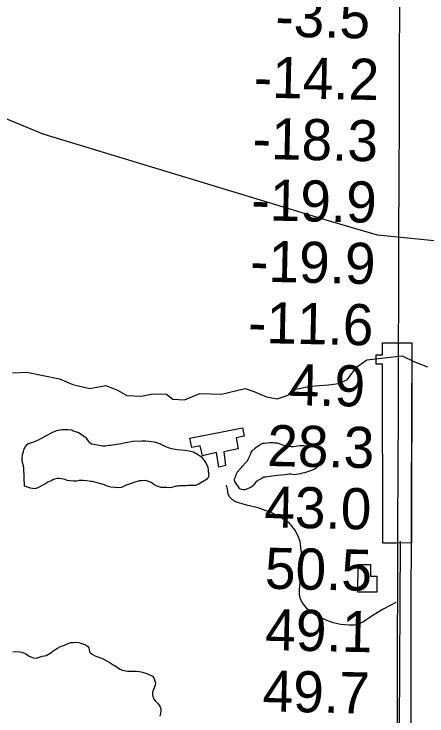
# Model space of a CAD drawing. Extents: x 3146026 to 3183936, y 897894 to 923344.
# Drawn here: x 3160093 to 3160766, y 910893 to 912037 of the extents above; entities that cross this region are included whole.
import ezdxf

# ---------------------------------------------------------------- set-up
doc = ezdxf.new("R2010")
doc.units = 0
for name, color, linetype in [('V-BLDG-OTLN', 7, 'Continuous'), ('V-CHAN-DOCK', 7, 'Continuous'), ('V-GRID-MAJR', 7, 'Continuous'), ('V-RIVR-EDGE', 7, 'Continuous'), ('V-RIVR-RANG', 7, 'Continuous'), ('V-ROAD-CNTR', 7, 'Continuous'), ('V-SITE-STRC', 7, 'Continuous'), ('V-SITE-VEGE', 7, 'Continuous'), ('V-TOPO-BNDY', 7, 'Continuous'), ('V-TOPO-SHOR', 7, 'Continuous')]:
    doc.layers.add(name, color=color, linetype=linetype)

msp = doc.modelspace()

# ---------------------------------------------------------------- linework, layer by layer
at = {"layer": 'V-BLDG-OTLN'}
msp.add_lwpolyline([(3160653.847000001, 911094.7049999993), (3160654.001000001, 911139.5099999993), (3160674.080000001, 911139.4399999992), (3160674.014000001, 911120.7769999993), (3160684.629000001, 911120.7399999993), (3160684.539000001, 911094.5969999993)], close=True, dxfattribs=at)
at = {"layer": 'V-CHAN-DOCK'}
msp.add_lwpolyline([(3160716.291000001, 911174.2719999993), (3160694.164000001, 911174.5569999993), (3160693.7690000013, 911466.0689999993), (3160683.320000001, 911466.2149999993), (3160683.646000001, 911481.3759999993), (3160693.888000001, 911481.6379999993), (3160693.779000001, 911500.8959999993), (3160741.510000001, 911500.9569999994), (3160740.869000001, 911174.8169999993), (3160716.291000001, 911174.2719999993)], dxfattribs=at)
msp.add_lwpolyline([(3160427.261000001, 911298.0469999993), (3160423.441000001, 911322.1989999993), (3160400.119000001, 911316.5389999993), (3160396.3400000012, 911332.9059999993), (3160383.040000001, 911330.1679999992), (3160379.471000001, 911345.5139999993), (3160465.827000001, 911362.5879999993), (3160468.563000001, 911349.0809999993), (3160455.470000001, 911345.9359999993), (3160458.642000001, 911328.3349999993), (3160434.906000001, 911323.2889999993), (3160437.898000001, 911300.9759999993)], close=True, dxfattribs=at)
at = {"layer": 'V-GRID-MAJR'}
msp.add_spline([(3160706.023, 907303.2220000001), (3160713.04, 909400.895), (3160733.322, 915463.759), (3160753.6040000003, 921526.669), (3160753.614, 921529.706)], degree=3, dxfattribs=at)
at = {"layer": 'V-RIVR-EDGE'}
msp.add_lwpolyline([(3160090.500730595, 911452.2093146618), (3160114.2982461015, 911452.9436602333), (3160167.416153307, 911442.5008450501), (3160189.2052088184, 911432.9286871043), (3160216.5544055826, 911426.5155404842), (3160242.7422637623, 911431.606520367), (3160261.7590939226, 911423.6275973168), (3160276.808037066, 911414.8652957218), (3160300.6016299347, 911414.013271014), (3160319.25128731, 911417.9331057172), (3160341.8551024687, 911417.0840229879), (3160352.146896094, 911409.1266744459), (3160370.7838048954, 911407.890805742), (3160395.7956145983, 911418.5370235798), (3160431.4860039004, 911417.2589865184), (3160469.9780383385, 911426.2854916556), (3160484.244583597, 911421.8876696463), (3160504.449230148, 911413.1126194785), (3160522.287069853, 911409.4991566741), (3160540.149426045, 911415.8005081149), (3160546.9120935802, 911424.1122808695), (3160576.2756342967, 911430.3851931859), (3160606.0249803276, 911432.2946065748), (3160621.894567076, 911434.6349356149), (3160636.5851633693, 911441.340724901), (3160651.3091020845, 911461.5306615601), (3160668.3920023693, 911473.3862702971), (3160725.9145962, 911479.9861483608), (3160745.719708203, 911470.0223011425), (3160767.1160937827, 911462.0374941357)], dxfattribs=at)
at = {"layer": 'V-ROAD-CNTR'}
for points in [[(3160715.496000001, 911077.7909999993), (3160695.002000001, 911067.1049999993), (3160675.296000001, 911055.0279999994), (3160662.818000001, 911046.3599999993), (3160655.351000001, 911042.9299999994), (3160647.370000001, 911040.9929999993), (3160639.180000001, 911040.6199999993), (3160625.681000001, 911042.0119999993), (3160613.610000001, 911044.8429999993), (3160602.047000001, 911049.1349999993), (3160598.672000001, 911050.7139999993), (3160588.989000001, 911054.7649999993), (3160579.968000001, 911060.2269999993), (3160571.813000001, 911066.9759999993), (3160567.006000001, 911072.0479999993), (3160562.744000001, 911077.9219999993), (3160559.861000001, 911084.5919999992), (3160558.497000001, 911091.7379999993), (3160558.665000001, 911098.6339999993), (3160561.827000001, 911132.9049999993), (3160562.322000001, 911140.6479999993), (3160561.6610000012, 911158.7999999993), (3160559.660000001, 911177.3029999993), (3160555.976000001, 911187.0989999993), (3160550.856000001, 911196.2229999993), (3160544.423000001, 911204.4639999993), (3160542.082000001, 911206.9109999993), (3160528.795000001, 911215.6849999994), (3160514.704000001, 911223.0879999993), (3160499.948000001, 911229.0499999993), (3160491.138000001, 911231.8229999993), (3160471.872000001, 911236.3939999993), (3160454.206000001, 911242.0649999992), (3160449.062000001, 911245.1109999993), (3160444.898000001, 911249.3849999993), (3160442.049000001, 911254.4949999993), (3160441.382000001, 911262.6559999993), (3160439.7150000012, 911269.2319999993)], [(3160722.593518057, 911177.624616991), (3160721.038521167, 910872.1702279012)]]:
    msp.add_lwpolyline(points, dxfattribs=at)
at = {"layer": 'V-SITE-STRC'}
for p, q in [((3160741.510000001, 911500.9569999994), (3160740.601000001, 911241.4099999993)), ((3160740.601000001, 911241.4099999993), (3160740.181000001, 911022.8229999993)), ((3160740.181000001, 911022.8229999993), (3160739.978000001, 910838.4489999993))]:
    msp.add_line(p, q, dxfattribs=at)
at = {"layer": 'V-SITE-VEGE'}
for points in [[(3160398.812000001, 911315.2999999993), (3160406.003000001, 911305.2689999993), (3160408.978000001, 911298.1559999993), (3160409.849000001, 911293.1239999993), (3160409.859000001, 911291.0249999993), (3160410.717000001, 911287.2539999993), (3160410.312000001, 911284.7329999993), (3160410.326000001, 911282.2159999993), (3160408.657000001, 911280.5289999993), (3160406.992000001, 911278.4209999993), (3160397.790000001, 911272.9159999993), (3160393.192000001, 911269.9549999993), (3160389.004000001, 911268.6709999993), (3160381.453000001, 911268.2099999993), (3160377.259000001, 911268.1849999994), (3160373.904000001, 911267.7469999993), (3160371.383000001, 911268.1529999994), (3160369.288000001, 911267.7229999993), (3160366.771000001, 911267.7079999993), (3160362.995000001, 911267.6879999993), (3160360.480000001, 911267.2539999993), (3160357.963000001, 911267.2389999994), (3160350.002000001, 911265.0969999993), (3160345.810000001, 911264.6549999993), (3160341.611000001, 911265.0519999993), (3160338.675000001, 911265.0339999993), (3160332.799000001, 911265.4209999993), (3160326.493000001, 911267.4849999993), (3160323.128000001, 911269.1439999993), (3160321.025000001, 911269.9709999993), (3160316.810000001, 911273.3029999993), (3160309.663000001, 911276.2009999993), (3160306.724000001, 911276.6049999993), (3160300.850000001, 911276.1519999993), (3160297.495000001, 911276.1339999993), (3160295.398000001, 911275.7019999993), (3160291.630000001, 911274.4239999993), (3160288.699000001, 911273.1479999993), (3160284.091000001, 911271.8639999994), (3160276.137000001, 911268.8819999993), (3160268.187000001, 911265.0599999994), (3160261.895000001, 911264.6079999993), (3160257.277000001, 911265.0009999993), (3160250.979000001, 911265.8059999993), (3160246.779000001, 911266.6209999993), (3160239.627000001, 911269.9359999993), (3160236.266000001, 911270.7579999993), (3160223.239000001, 911274.4599999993), (3160220.300000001, 911274.8659999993), (3160217.781000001, 911274.8499999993), (3160211.901000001, 911276.0759999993), (3160205.186000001, 911276.4569999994), (3160199.312000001, 911276.4269999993), (3160195.542000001, 911275.5659999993), (3160190.086000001, 911275.5359999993), (3160184.630000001, 911275.9249999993), (3160179.5900000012, 911276.7359999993), (3160176.647000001, 911277.9789999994), (3160170.345000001, 911279.2019999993), (3160166.147000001, 911280.0169999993), (3160163.208000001, 911279.9999999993), (3160159.020000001, 911278.7179999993), (3160156.509000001, 911277.4459999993), (3160154.418000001, 911276.1749999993), (3160150.650000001, 911274.8969999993), (3160148.141000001, 911273.6229999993), (3160143.121000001, 911270.6569999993), (3160137.684000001, 911267.6919999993), (3160134.3400000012, 911265.5739999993), (3160129.316000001, 911263.4479999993), (3160126.801000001, 911263.0139999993), (3160120.079000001, 911264.2369999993), (3160116.719000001, 911265.0559999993), (3160110.413000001, 911267.5379999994), (3160109.493000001, 911281.7979999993), (3160109.4110000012, 911296.4829999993), (3160108.549000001, 911300.6749999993), (3160106.843000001, 911305.7009999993), (3160106.403000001, 911309.4729999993), (3160106.386000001, 911312.4119999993), (3160107.189000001, 911318.7099999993), (3160108.420000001, 911323.7519999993), (3160109.657000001, 911327.9539999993), (3160111.730000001, 911332.1609999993), (3160115.901000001, 911336.3799999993), (3160118.834000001, 911337.2359999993), (3160125.533000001, 911339.7899999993), (3160130.557000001, 911341.9149999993), (3160133.070000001, 911342.7689999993), (3160145.198000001, 911349.5499999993), (3160155.241000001, 911354.6419999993), (3160162.354000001, 911358.0369999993), (3160171.156000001, 911359.7619999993), (3160180.807000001, 911359.8169999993), (3160187.524000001, 911359.0159999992), (3160189.627000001, 911357.7689999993), (3160198.0360000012, 911354.8789999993), (3160204.350000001, 911351.1379999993), (3160207.725000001, 911348.2189999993), (3160209.409000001, 911346.9719999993), (3160214.4820000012, 911340.2849999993)], [(3160214.4820000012, 911340.2849999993), (3160217.433000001, 911337.7869999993), (3160219.5360000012, 911336.5369999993), (3160229.197000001, 911334.9129999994), (3160237.1780000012, 911333.2789999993), (3160242.214000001, 911332.8879999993), (3160248.4990000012, 911334.1819999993), (3160250.598000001, 911334.1919999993), (3160260.658000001, 911335.9269999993), (3160268.205000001, 911336.8099999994), (3160272.813000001, 911338.0939999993), (3160287.065000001, 911340.6909999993), (3160301.7490000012, 911341.1899999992), (3160308.039000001, 911341.2249999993), (3160312.239000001, 911340.8299999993), (3160321.476000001, 911339.6239999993), (3160326.940000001, 911337.9749999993), (3160331.564000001, 911336.3219999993), (3160339.979000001, 911332.1729999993), (3160345.867000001, 911329.6889999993), (3160349.648000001, 911328.8719999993), (3160358.886000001, 911327.2439999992), (3160372.319000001, 911326.0599999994), (3160378.621000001, 911324.8369999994), (3160382.823000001, 911323.5999999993), (3160385.762000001, 911323.1989999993), (3160393.760000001, 911318.6279999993), (3160398.812000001, 911315.2999999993)]]:
    msp.add_lwpolyline(points, dxfattribs=at)
msp.add_lwpolyline([(3160461.202000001, 911262.7809999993), (3160453.164000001, 911274.9029999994), (3160452.728000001, 911277.8379999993), (3160453.133000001, 911280.3569999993), (3160454.792000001, 911283.7239999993), (3160455.202000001, 911285.8229999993), (3160456.856000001, 911290.0269999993), (3160461.022000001, 911295.0859999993), (3160463.945000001, 911298.0389999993), (3160465.610000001, 911300.1469999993), (3160470.199000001, 911304.7869999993), (3160473.535000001, 911308.5819999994), (3160475.612000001, 911312.3709999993), (3160478.926000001, 911319.9399999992), (3160479.751000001, 911322.4639999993), (3160481.418000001, 911324.9909999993), (3160483.501000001, 911327.0979999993), (3160485.5900000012, 911328.3699999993), (3160487.259000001, 911330.4769999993), (3160495.619000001, 911335.9779999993), (3160498.970000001, 911337.2539999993), (3160501.484000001, 911337.2689999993), (3160510.291000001, 911338.5769999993), (3160515.745000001, 911338.6079999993), (3160517.846000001, 911338.1999999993), (3160522.042000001, 911337.8029999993), (3160526.247000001, 911336.5679999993), (3160532.5530000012, 911334.0859999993), (3160535.913000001, 911333.2649999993), (3160544.312000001, 911332.0519999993), (3160548.509000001, 911332.0769999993), (3160558.990000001, 911333.3939999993), (3160565.704000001, 911333.4329999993), (3160568.640000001, 911333.0269999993), (3160572.419000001, 911333.0499999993), (3160579.136000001, 911332.2469999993), (3160584.177000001, 911331.0179999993), (3160588.805000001, 911328.9449999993), (3160591.754000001, 911326.8629999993), (3160593.8570000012, 911325.6149999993), (3160596.815000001, 911322.2749999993), (3160597.245000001, 911320.1799999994), (3160597.257000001, 911318.0829999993), (3160596.862000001, 911313.8839999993), (3160596.880000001, 911310.5279999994), (3160594.390000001, 911305.4799999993), (3160591.467000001, 911302.9459999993), (3160586.462000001, 911297.4639999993), (3160583.955000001, 911295.7719999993), (3160578.094000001, 911292.8019999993), (3160571.395000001, 911290.6659999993), (3160566.789000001, 911288.9619999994), (3160563.017000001, 911288.5199999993), (3160560.082000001, 911287.6659999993), (3160550.024000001, 911285.9309999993), (3160544.984000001, 911286.7419999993), (3160541.627000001, 911286.7239999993), (3160534.920000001, 911285.8469999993), (3160521.917000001, 911284.9359999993), (3160518.987000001, 911284.0819999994), (3160513.535000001, 911283.6289999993), (3160503.473000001, 911281.8969999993), (3160500.116000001, 911281.8779999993), (3160497.608000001, 911280.6039999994), (3160487.986000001, 911275.0969999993), (3160483.823000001, 911269.6189999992), (3160482.157000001, 911267.0939999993), (3160479.233000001, 911264.9779999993), (3160469.601000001, 911261.5679999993), (3160466.664000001, 911261.5519999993), (3160463.725000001, 911261.9549999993)], close=True, dxfattribs=at)
at = {"layer": 'V-TOPO-BNDY'}
msp.add_lwpolyline([(3162288.0485607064, 912035.1193577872), (3162225.514274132, 912006.2645998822), (3162087.305464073, 911943.1889477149), (3161778.1195046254, 911799.8221818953), (3161261.5298716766, 911668.3447235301), (3160960.59504134, 911648.5365415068), (3160815.943860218, 911663.2946838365), (3160685.64507727, 911676.589578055), (3160605.8988812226, 911699.9980547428), (3160140.638647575, 911840.9391507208), (3159445.187113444, 912129.3016423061), (3158861.879770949, 912432.7324246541), (3158245.4111681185, 912823.6388573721), (3157767.9295387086, 913092.6725836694), (3157135.275562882, 913454.6088522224), (3156545.813290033, 913785.7040784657)], dxfattribs=at)
at = {"layer": 'V-TOPO-SHOR'}
for points in [[(3160129.389000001, 910987.2899999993), (3160139.208000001, 910990.2119999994), (3160142.687000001, 910990.6399999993), (3160145.755000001, 910991.2729999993), (3160151.881000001, 910995.1989999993), (3160154.535000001, 910996.6469999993), (3160157.187000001, 910998.7119999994), (3160164.128000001, 911003.2559999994), (3160167.804000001, 911005.3269999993), (3160170.663000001, 911006.7769999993), (3160174.343000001, 911007.8209999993), (3160181.497000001, 911011.1389999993), (3160186.201000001, 911012.3919999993), (3160190.295000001, 911012.8259999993), (3160194.393000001, 911012.8489999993), (3160198.2860000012, 911012.4619999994), (3160201.981000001, 911011.4559999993), (3160209.780000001, 911008.6319999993), (3160213.069000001, 911006.8069999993), (3160215.133000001, 911003.7459999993), (3160215.561000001, 911000.6759999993), (3160216.192000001, 910997.6059999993), (3160218.252000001, 910995.3629999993), (3160220.722000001, 910993.5339999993), (3160226.475000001, 910990.4929999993), (3160233.866000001, 910987.4619999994), (3160237.356000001, 910986.2519999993), (3160250.918000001, 910978.9529999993), (3160253.592000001, 910976.9189999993), (3160256.677000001, 910974.8869999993), (3160265.926000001, 910969.2019999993), (3160269.417000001, 910967.5819999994), (3160272.700000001, 910966.7809999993), (3160278.031000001, 910965.7879999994), (3160281.720000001, 910965.6039999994), (3160292.165000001, 910966.0709999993), (3160297.086000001, 910965.4849999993), (3160300.572000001, 910964.8889999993), (3160304.469000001, 910963.8849999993), (3160308.164000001, 910962.4719999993), (3160311.655000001, 910961.0569999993), (3160318.844000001, 910957.6159999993), (3160321.113000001, 910954.7619999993), (3160324.027000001, 910946.5819999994), (3160323.431000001, 910943.0959999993), (3160318.989000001, 910931.6009999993), (3160319.008000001, 910928.1169999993), (3160319.643000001, 910924.6379999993), (3160321.101000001, 910920.1379999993), (3160322.960000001, 910917.4879999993), (3160325.637000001, 910915.0429999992), (3160328.109000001, 910912.3949999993), (3160330.587000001, 910908.9249999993), (3160332.457000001, 910904.2229999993), (3160332.477000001, 910900.7409999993), (3160331.885000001, 910896.6409999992), (3160330.679000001, 910892.5369999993)], [(3160091.229000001, 910997.5239999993), (3160096.1440000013, 910997.7569999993), (3160102.495000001, 910997.5869999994), (3160105.983000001, 910996.9909999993), (3160112.5530000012, 910994.1609999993), (3160117.900000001, 910990.5029999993), (3160124.265000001, 910987.6709999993), (3160129.389000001, 910987.2899999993)]]:
    msp.add_lwpolyline(points, dxfattribs=at)

# ---------------------------------------------------------------- texts
at = {"layer": 'V-RIVR-RANG'}
for s, p in [('-3.5', (3160518.651953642, 912000.1533896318)), ('-14.2', (3160483.5352881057, 911900.8800065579)), ('-18.3', (3160481.6462881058, 911800.898006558)), ('-19.9', (3160479.4935685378, 911700.9206305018)), ('-19.9', (3160477.605568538, 911600.9386305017)), ('-11.6', (3160474.134251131, 911500.9903741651)), ('4.9', (3160540.285899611, 911399.5573966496)), ('28.3', (3160505.431953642, 911300.2783896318)), ('43.0', (3160500.6430383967, 911200.3582530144)), ('50.5', (3160501.654953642, 911100.3133896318)), ('49.1', (3160502.140429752, 911000.280774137)), ('49.7', (3160497.877953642, 910900.3493896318))]:
    msp.add_text(s, height=66.99999999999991, rotation=358.77832571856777, dxfattribs=at).set_placement(p)

doc.saveas('drawing.dxf')
